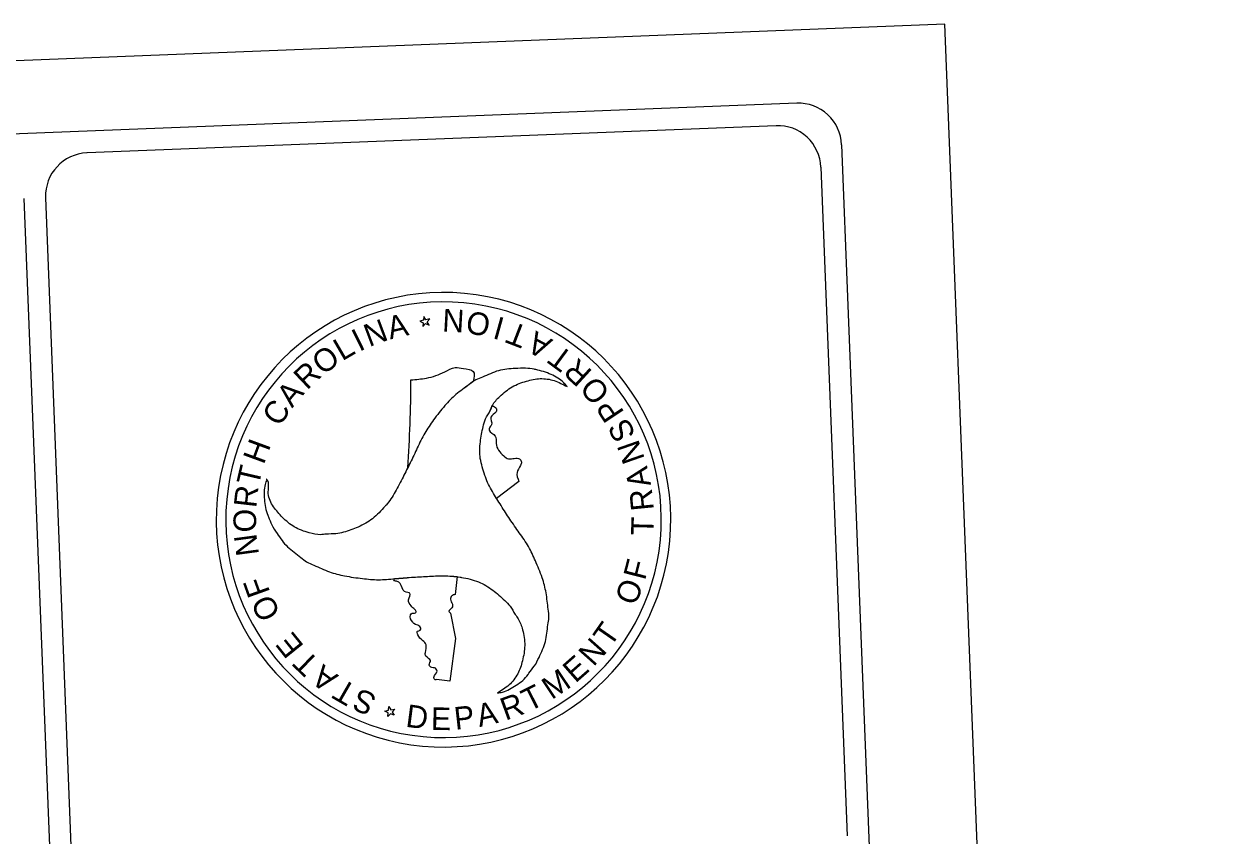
# Model space of a CAD drawing. Extents: x 1624323 to 1631382, y 753034 to 769560.
# Drawn here: x 1629687 to 1631382, y 766642 to 767782 of the extents above; entities that cross this region are included whole.
import ezdxf

# ---------------------------------------------------------------- set-up
doc = ezdxf.new("R2010")
doc.units = 0
doc.layers.add('Sheet Plot Border Outside CELL', color=7, linetype='Continuous')
doc.layers.add('Sheet Title CELL', color=7, linetype='Continuous')

msp = doc.modelspace()

# ---------------------------------------------------------------- linework, layer by layer
at = {"layer": 'Sheet Plot Border Outside CELL'}
msp.add_lwpolyline([(1624322.9, 767519.9), (1624724.8, 757327.8), (1631382.3, 757590.3), (1630980.3, 767782.4)], close=True, dxfattribs=at)
at = {"layer": 'Sheet Title CELL'}
for p, q in [((1630025.6, 758943.2), (1629686.7, 767537.4)), ((1629754, 766599.1), (1629717, 767538.6)), ((1630305.5, 767404.1), (1630305.5, 767404.1)), ((1630248.1, 767371.9), (1630247.8, 767366.5)), ((1630251.1, 767367.2), (1630248.1, 767371.9)), ((1630256.5, 767368.3), (1630251.1, 767367.2)), ((1630252.9, 767364.2), (1630256.5, 767368.3)), ((1630247.8, 767366.5), (1630242.5, 767365.1)), ((1630242.5, 767365.1), (1630247.5, 767363)), ((1630247.5, 767363), (1630247, 767357.5)), ((1630247, 767357.5), (1630250.6, 767361.7)), ((1630250.6, 767361.7), (1630255.7, 767359.6)), ((1630255.7, 767359.6), (1630252.9, 767364.2)), ((1630225.6, 767159.2), (1630225.6, 767159.2)), ((1630027.2, 767143.4), (1630027.8, 767142.7)), ((1630027.2, 767143.4), (1630027.8, 767142.7)), ((1630381.8, 767140.1), (1630350.4, 767116.1)), ((1630350.4, 767116.1), (1630350.4, 767116.1)), ((1630294.9, 767006.4), (1630292.3, 766981.2)), ((1630285.9, 766955), (1630292.8, 766919.5)), ((1630292.8, 766919.5), (1630285, 766859.4)), ((1630285, 766859.4), (1630265.9, 766861.8)), ((1630193.3, 766817.1), (1630198.6, 766818.5)), ((1630198.2, 766815.1), (1630193.3, 766817.1)), ((1630197.7, 766809.6), (1630198.2, 766815.1)), ((1630201.4, 766813.7), (1630197.7, 766809.6)), ((1630198.6, 766818.5), (1630199.1, 766824)), ((1630199.1, 766824), (1630201.9, 766819.1)), ((1630206.6, 766811.6), (1630201.4, 766813.7)), ((1630201.9, 766819.1), (1630207.4, 766820.3)), ((1630207.4, 766820.3), (1630203.7, 766816.1)), ((1630203.7, 766816.1), (1630206.6, 766811.6))]:
    msp.add_line(p, q, dxfattribs=at)
for points in [[(1630772.6, 767671.2), (1624538.8, 767425.4)], [(1630743.5, 767639.7), (1629775.1, 767601.5)], [(1631188.8, 758655.6), (1630835.6, 767613)], [(1630843.5, 766642.1), (1630806.4, 767581.6)]]:
    msp.add_lwpolyline(points, dxfattribs=at)
for centre, radius, start, end in [((1630774.7, 767610.7), 60.6, 2.2582, 92.2582), ((1630745.6, 767579.2), 60.6, 2.2582, 92.2582), ((1629777.3, 767541), 60.6, 92.2582, 182.2582), ((1630275.9, 767086.2), 319.3, 84.6793, 264.6793), ((1630275.9, 767086.2), 319.3, 264.6793, 84.6793), ((1630275.9, 767086.2), 306, 84.6793, 264.6793), ((1630275.9, 767086.2), 306, 264.6793, 84.6793), ((1628546.6, 767282.6), 1683.5, 355.7969, 0.0029), ((1628546.6, 767282.6), 1683.5, 350.3578, 350.4574)]:
    msp.add_arc(centre, radius, start, end, dxfattribs=at)
for points in [[(1630449.5, 767273.2), (1630444.9, 767278.6), (1630427.1, 767290.3), (1630405.5, 767297.2), (1630403.3, 767297.7), (1630391.2, 767299), (1630376.8, 767298.7), (1630353.3, 767295.6), (1630330.9, 767286.6), (1630321.5, 767282.8), (1630312.1, 767276.2), (1630293.4, 767262), (1630277.8, 767246.5), (1630262, 767226.4), (1630249.6, 767207.9), (1630239.1, 767187.1), (1630229.1, 767166.2), (1630219, 767146.2), (1630208.1, 767125.3), (1630195.1, 767106.8), (1630193.7, 767105.3), (1630176.3, 767087.6), (1630155.9, 767076), (1630135.4, 767068.6), (1630124.6, 767066.5), (1630111, 767065.9), (1630103.1, 767065.2), (1630087.2, 767067.8), (1630066.2, 767076.2), (1630049.7, 767089.5), (1630037.1, 767104.4), (1630029.7, 767122.9), (1630027.8, 767142.7), (1630027.2, 767143.4)], [(1630230.2, 767282.6), (1630251.8, 767285.2), (1630277.8, 767294), (1630292.2, 767299.9), (1630303.9, 767298.6), (1630317.7, 767294.5), (1630317.8, 767280.8)], [(1630351.6, 766842.6), (1630358.9, 766844.2), (1630377.9, 766853.7), (1630394.7, 766868.9), (1630395.8, 766870.6), (1630403.5, 766880.4), (1630410.1, 766892.9), (1630419.2, 766915.1), (1630422.6, 766938.7), (1630424, 766948.7), (1630423, 766960.5), (1630420, 766983.4), (1630414.5, 767004.7), (1630405, 767028.5), (1630395.3, 767048.4), (1630382.4, 767067.9), (1630369.1, 767087), (1630356.9, 767106), (1630344.6, 767125.7), (1630334.8, 767146.3), (1630334.1, 767148.5), (1630327.6, 767172.3), (1630327.7, 767195.5), (1630331.6, 767216.8), (1630335, 767227.8), (1630341.5, 767239.5), (1630344.7, 767246.9), (1630354.9, 767259.3), (1630372.6, 767273), (1630392.4, 767280.8), (1630411.8, 767284.4), (1630431.4, 767281.6), (1630449.5, 767273.2)], [(1630317.9, 767280.7), (1630312.1, 767276.2), (1630293.4, 767262), (1630277.8, 767246.5), (1630262, 767226.4), (1630249.6, 767207.9), (1630239.1, 767187.1), (1630229.1, 767166.2), (1630225.6, 767159.2)], [(1630350.4, 767116.1), (1630344.6, 767125.7), (1630334.8, 767146.3), (1630334.1, 767148.5), (1630327.6, 767172.3), (1630327.7, 767195.5), (1630331.6, 767216.8), (1630335, 767227.8), (1630341.5, 767239.5), (1630344.6, 767246.3)], [(1630344.7, 767246.2), (1630349.9, 767242.8), (1630349.9, 767237.9), (1630342.4, 767230.2), (1630343.5, 767219.7), (1630340.4, 767215.3), (1630340, 767212.1), (1630348.6, 767203.8), (1630349.9, 767193.4), (1630360.5, 767175.8), (1630367.3, 767171.8), (1630382.7, 767171.6), (1630385.3, 767167.2), (1630384.1, 767162.4), (1630379.2, 767152.6), (1630381.8, 767140.1)], [(1630027.8, 767142.7), (1630025.3, 767135.8), (1630024.2, 767114.6), (1630029, 767092.4), (1630029.9, 767090.5), (1630034.5, 767079.2), (1630042, 767067), (1630056.7, 767048.2), (1630075.5, 767033.2), (1630083.6, 767027.1), (1630093.8, 767022.3), (1630115.6, 767013.1), (1630136.9, 767007.4), (1630162.1, 767003.6), (1630184.4, 767001.9), (1630207.4, 767003.5), (1630230.7, 767005.3), (1630253.2, 767006.6), (1630276.4, 767007.5), (1630299.1, 767005.5), (1630301.1, 767005.2), (1630325, 766998.9), (1630345.2, 766987.1), (1630361.9, 766972.9), (1630369.4, 766964.7), (1630376.7, 766953.2), (1630380.9, 766946.8), (1630386.9, 766931.7), (1630390, 766909.4), (1630386.8, 766888.2), (1630380.2, 766869.8), (1630368, 766854.2), (1630351.6, 766842.6)], [(1630265.9, 766861.8), (1630264, 766861.4), (1630262.3, 766864.8), (1630266.8, 766873.4), (1630263.3, 766878.2), (1630259.5, 766878.4), (1630255.9, 766882.4), (1630257.7, 766888.4), (1630251.2, 766894.6), (1630250.4, 766899.8), (1630251.4, 766910.5), (1630239.8, 766924.4), (1630239.5, 766929.9), (1630243.1, 766930.9), (1630244, 766934.1), (1630234, 766940.6), (1630232.6, 766942.1), (1630229.6, 766952.5), (1630231.7, 766955), (1630236.5, 766955.3), (1630237.6, 766956.6), (1630235.5, 766960.1), (1630230.3, 766965.1), (1630226.8, 766973.7), (1630228.8, 766982.9), (1630221.3, 766985.2), (1630215, 766996.8), (1630210.8, 766999.5), (1630206.3, 767000.5)], [(1630206.9, 767003.5), (1630207.4, 767003.5), (1630230.7, 767005.3), (1630253.2, 767006.6), (1630276.4, 767007.5), (1630294.9, 767006.3)], [(1630292.3, 766981.2), (1630287.5, 766979.2), (1630285.6, 766974.5), (1630288.5, 766967.5), (1630287.7, 766962.6), (1630283.3, 766957.5), (1630285.9, 766955)]]:
    msp.add_spline(points, degree=3, dxfattribs=at)

# ---------------------------------------------------------------- texts
for s, height, rotation, p in [('N', 31.8, 20.5747, (1630171.5, 767328.6)), ('A', 31.8, 13.1427, (1630200.9, 767339.4)), ('N', 31.8, 176.8875, (1630306, 767380.8)), ('O', 31.7, 169.6394, (1630343.8, 767374.2)), ('I', 31.9, 164.5038, (1630363.6, 767369)), ('I', 31.9, 26.2748, (1630157.5, 767321.9)), ('T', 31.8, 158.8539, (1630397.2, 767356.1)), ('A', 31.9, 151.7695, (1630430.6, 767338.7)), ('L', 31.8, 30.2641, (1630133.5, 767308.6)), ('O', 31.9, 36.4978, (1630106.2, 767288.4)), ('T', 31.7, 143.6824, (1630460.1, 767317.8)), ('R', 31.8, 43.6174, (1630084.1, 767267.4)), ('R', 31.9, 137.5826, (1630486.4, 767294.3)), ('O', 31.9, 130.3935, (1630511.5, 767265.2)), ('A', 31.8, 49.9813, (1630063.1, 767242.4)), ('C', 31.7, 57.4784, (1630045.9, 767215.7)), ('P', 31.8, 123.7016, (1630530.7, 767237)), ('S', 31.7, 116.5097, (1630546.6, 767205.6)), ('H', 31.8, 69.8207, (1630023.3, 767162.7)), ('N', 31.7, 109.2992, (1630559.1, 767171.8)), ('T', 31.9, 76.9054, (1630016, 767132.3)), ('A', 31.7, 102.2676, (1630567.7, 767135.1)), ('R', 31.8, 83.5551, (1630012.6, 767102.1)), ('R', 31.9, 95.5145, (1630571.5, 767100.2)), ('O', 31.9, 90.165, (1630012.7, 767068.4)), ('T', 31.7, 88.5578, (1630571, 767064.1)), ('N', 31.8, 97.6631, (1630016.7, 767037.5)), ('F', 31.8, 75.6486, (1630559, 767000.1)), ('F', 31.9, 109.75, (1630032.6, 766984.4)), ('O', 31.8, 68.4834, (1630545.4, 766964.1)), ('O', 31.9, 116.8969, (1630047.6, 766954.3)), ('T', 31.8, 55.1797, (1630510.4, 766905.9)), ('E', 31.7, 128.8363, (1630080.8, 766908.6)), ('N', 31.9, 48.3377, (1630486.8, 766878.8)), ('T', 31.8, 135.9519, (1630103.1, 766886.9)), ('E', 31.8, 41.3662, (1630461.2, 766855.8)), ('A', 31.9, 143.0071, (1630129.4, 766867.1)), ('M', 31.7, 33.8994, (1630428, 766832.7)), ('T', 31.9, 150.0594, (1630156.2, 766851.2)), ('S', 31.8, 156.4356, (1630183.9, 766839)), ('R', 31.8, 20.0138, (1630363, 766803.7)), ('T', 31.8, 26.6643, (1630395.9, 766816)), ('D', 31.8, 352.5323, (1630221.7, 766795.5)), ('P', 31.8, 6.3526, (1630292.6, 766791)), ('A', 31.8, 12.9452, (1630326.4, 766794.8)), ('E', 31.7, 358.8202, (1630258, 766791.1))]:
    msp.add_text(s, height=height, rotation=rotation, dxfattribs=at).set_placement(p)

doc.saveas('drawing.dxf')
